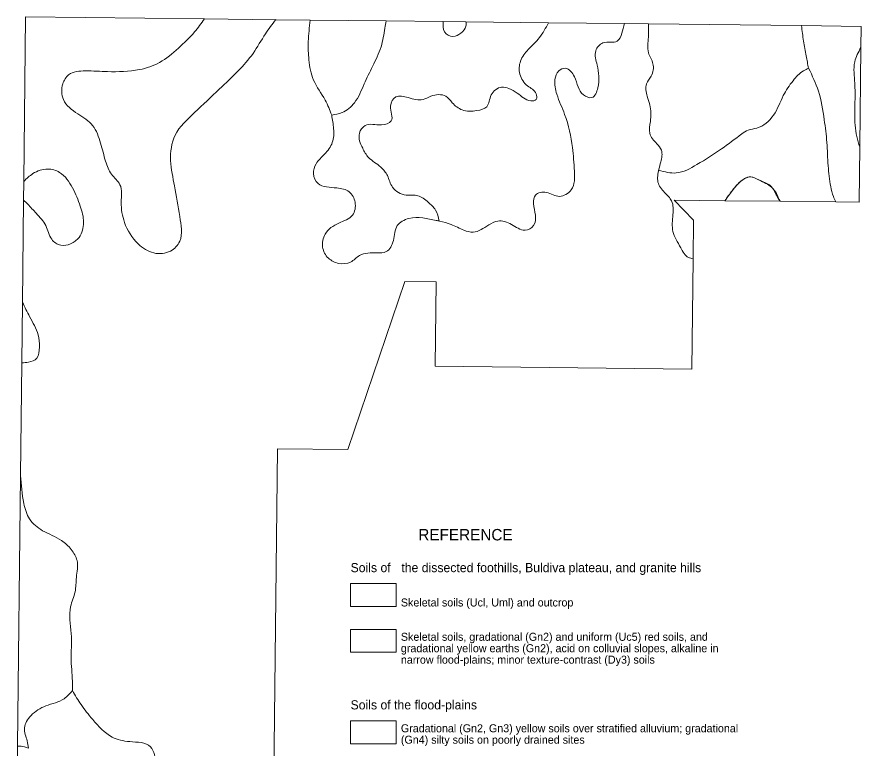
# Model space of a CAD drawing. Extents: x 796677 to 815296, y 8501154 to 8534584.
# Drawn here: x 796836 to 815296, y 8518597 to 8534584 of the extents above; entities that cross this region are included whole.
import ezdxf

# ---------------------------------------------------------------- set-up
doc = ezdxf.new("R2010")
doc.units = 0
doc.header["$LTSCALE"] = 70
for name, color, linetype, lineweight in [('30', 7, 'Continuous', 13), ('31', 7, 'Continuous', 13), ('32', 7, 'Continuous', 13), ('33', 7, 'Continuous', 13)]:
    doc.layers.add(name, color=color, linetype=linetype, lineweight=lineweight)
doc.layers.add('60', color=7, linetype='Continuous')

msp = doc.modelspace()

# ---------------------------------------------------------------- linework, layer by layer
at = {"layer": '30'}
for p, q in [((803251.08, 8534513.12), (802496.87, 8534521.65)), ((810645.75, 8534429.48), (810120.03, 8534435.43)), ((796983.21, 8530574.07), (796958.24, 8528327.65)), ((812316.38, 8530565.37), (813523.7, 8530551.45)), ((796943.71, 8527020.93), (796916.34, 8524559.34))]:
    msp.add_line(p, q, dxfattribs=at)
for points in [[(800936.16, 8534539.3), (797027.79, 8534583.51), (796987.84, 8530990.1)], [(802270.49, 8501474.58), (802331.51, 8506844.03), (800525.82, 8506864.46), (800607.09, 8514090.19), (802413.3, 8514069.87), (802537.73, 8525140.62), (804070.16, 8525123.41), (805316.55, 8528800.06), (806000.72, 8528792.3), (805979.73, 8526947.23), (811593.82, 8526882.94), (811621.58, 8529294.51)]]:
    msp.add_lwpolyline(points, dxfattribs=at)
msp.add_lwpolyline([(804132.47, 8521693.59), (805132.47, 8521693.59), (805132.47, 8522193.59), (804132.47, 8522193.59)], close=True, dxfattribs=at)
for points in [[(802498.04, 8534525.08), (802270.81, 8534212.39), (802000.97, 8533786), (801674.33, 8533402.25), (801262.48, 8533004.29), (800722.81, 8532492.62), (800296.76, 8531995.16), (800197.34, 8531440.85), (800282.55, 8530886.54), (800396.17, 8530218.53), (800396.17, 8529678.44), (800197.34, 8529465.24), (799828.1, 8529422.6), (799487.25, 8529621.59), (799189.01, 8530090.62), (799118.01, 8530531.22), (799089.6, 8530914.97), (798904.98, 8531142.38), (798777.16, 8531426.64), (798663.55, 8531824.6), (798493.13, 8532208.36), (798166.48, 8532464.19), (797854.04, 8532776.88), (797839.84, 8533117.99), (797967.66, 8533316.97), (798336.91, 8533402.25), (798819.77, 8533388.04), (799515.66, 8533430.68), (799955.91, 8533587.02), (800367.76, 8533899.71), (800722.81, 8534255.03), (800936.16, 8534539.3)], [(803719.39, 8532435.76), (803577.37, 8532762.66), (803321.74, 8533203.27), (803222.33, 8533643.87), (803208.13, 8534041.84), (803251.08, 8534513.12)], [(810120.03, 8534435.43), (810063.44, 8534226.61), (809964.02, 8534056.05), (809651.58, 8534013.41), (809495.36, 8533842.85), (809523.77, 8533530.17), (809537.97, 8533032.71), (809410.15, 8532819.52), (809225.53, 8532876.37), (809026.7, 8533274.33), (808827.88, 8533459.1), (808685.86, 8533402.25), (808600.65, 8533217.48), (808643.26, 8532890.58), (808813.68, 8532449.98), (808984.1, 8531725.11), (809026.7, 8531213.44), (808955.69, 8530801.27), (808700.06, 8530659.14), (808416.03, 8530744.41), (808174.6, 8530687.56), (808131.99, 8530502.79), (808174.6, 8530246.96), (808131.99, 8530019.55), (807947.37, 8529920.06), (807649.13, 8530047.98), (807350.89, 8530119.04), (807152.07, 8530033.76), (806811.22, 8529877.42), (806612.4, 8529920.06), (806328.36, 8530047.98), (806076.89, 8530119.04)], [(810872.94, 8531256.08), (810915.54, 8531412.43), (810929.75, 8531668.26), (810830.33, 8531810.39), (810674.11, 8532037.8), (810688.32, 8532293.63), (810674.11, 8532663.17), (810617.31, 8532847.94), (810603.1, 8533117.99), (810702.52, 8533288.55), (810745.12, 8533558.59), (810645.71, 8533800.21), (810645.71, 8534141.33), (810645.75, 8534429.48)], [(806076.89, 8530119.04), (806005.88, 8530133.25), (805409.41, 8530175.89), (805153.77, 8530019.55), (805068.56, 8529692.65), (804912.34, 8529451.03), (804713.52, 8529422.6), (804330.07, 8529365.75), (804131.24, 8529223.62), (803875.61, 8529195.19), (803648.38, 8529308.9), (803520.57, 8529550.52), (803577.37, 8529834.78), (803875.61, 8530076.4), (804173.85, 8530246.96), (804230.66, 8530531.22), (804102.84, 8530758.63), (803833, 8530843.91), (803421.15, 8530943.4), (803321.74, 8531156.59), (803378.55, 8531369.79), (803563.17, 8531582.98), (803733.59, 8531838.82), (803762, 8532137.29), (803719.39, 8532435.76)], [(796987.8, 8530986.35), (797186.56, 8531156.59), (797513.2, 8531256.08), (797768.83, 8531185.02), (798052.87, 8530843.91), (798223.29, 8530445.94), (798294.3, 8530090.62), (798194.89, 8529763.72), (798010.26, 8529621.59), (797797.24, 8529593.16), (797598.41, 8529721.08), (797470.6, 8530019.55), (797257.57, 8530289.6), (797072.95, 8530488.58), (796983.21, 8530574.07)], [(811621.58, 8529294.51), (811521.5, 8529323.11), (811351.08, 8529536.31), (811180.66, 8529891.63), (811180.66, 8530261.17), (811152.26, 8530559.65), (810996.04, 8530744.41), (810854.02, 8530971.82), (810872.94, 8531256.08)], [(813523.7, 8530551.45), (813503.76, 8530584.62), (813458.14, 8530660.5), (813314.39, 8530890.46), (813205.55, 8530958.26), (813008.28, 8531044.99), (812881.22, 8531085.83), (812746.26, 8531048.44), (812604.56, 8530933.06), (812476.78, 8530782.95), (812316.38, 8530565.37)], [(796958.4, 8528342.58), (797115.55, 8528029.73), (797300.17, 8527631.76), (797328.58, 8527361.71), (797271.77, 8527120.09), (797087.15, 8527034.82), (796943.71, 8527020.93)], [(796916.34, 8524559.34), (796987.38, 8523948.02), (797115.2, 8523606.91), (797399.23, 8523351.07), (797811.09, 8523137.88), (798024.11, 8522938.89), (798151.93, 8522697.27), (798137.73, 8522327.73), (798109.32, 8522015.05), (798009.91, 8521688.15), (798024.11, 8521105.41), (798024.11, 8520508.47), (798052.52, 8519996.8), (798052.52, 8519854.67)], [(798052.52, 8519854.67), (798238.43, 8519549.61), (798494.06, 8519222.71), (798920.11, 8518838.96), (799303.56, 8518739.47), (799758.02, 8518625.77), (799843.23, 8518455.21), (799885.83, 8518142.52), (800042.05, 8517701.92), (800070.46, 8517318.17), (800013.65, 8516948.63), (799814.83, 8516536.45), (799417.18, 8516095.85), (798721.29, 8515655.24)]]:
    msp.add_spline(points, degree=3, dxfattribs=at)
at = {"layer": '31'}
for p, q in [((804912.48, 8534494.33), (803251.08, 8534513.12)), ((806158.24, 8534480.24), (806655.07, 8534474.62)), ((808458.79, 8534454.22), (810120.03, 8534435.43)), ((810645.75, 8534429.48), (813993.04, 8534391.62)), ((815290.42, 8533913.69), (815265.16, 8531739.23)), ((796958.4, 8528342.58), (796943.71, 8527020.93))]:
    msp.add_line(p, q, dxfattribs=at)
msp.add_lwpolyline([(800936.16, 8534539.3), (802498, 8534521.64), (802498.04, 8534525.08)], dxfattribs=at)
msp.add_lwpolyline([(804132.47, 8520693.59), (805132.47, 8520693.59), (805132.47, 8521193.59), (804132.47, 8521193.59)], close=True, dxfattribs=at)
for points in [[(802498.04, 8534525.08), (802270.81, 8534212.39), (802000.97, 8533786), (801674.33, 8533402.25), (801262.48, 8533004.29), (800722.81, 8532492.62), (800296.76, 8531995.16), (800197.34, 8531440.85), (800282.55, 8530886.54), (800396.17, 8530218.53), (800396.17, 8529678.44), (800197.34, 8529465.24), (799828.1, 8529422.6), (799487.25, 8529621.59), (799189.01, 8530090.62), (799118.01, 8530531.22), (799089.6, 8530914.97), (798904.98, 8531142.38), (798777.16, 8531426.64), (798663.55, 8531824.6), (798493.13, 8532208.36), (798166.48, 8532464.19), (797854.04, 8532776.88), (797839.84, 8533117.99), (797967.66, 8533316.97), (798336.91, 8533402.25), (798819.77, 8533388.04), (799515.66, 8533430.68), (799955.91, 8533587.02), (800367.76, 8533899.71), (800722.81, 8534255.03), (800936.16, 8534539.3)], [(803251.08, 8534513.12), (803208.13, 8534041.84), (803222.33, 8533643.87), (803321.74, 8533203.27), (803577.37, 8532762.66), (803719.39, 8532435.76)], [(803719.39, 8532435.76), (803946.62, 8532492.62), (804216.45, 8532705.81), (804429.48, 8533117.99), (804614.1, 8533501.74), (804798.73, 8533928.13), (804883.94, 8534340.31), (804912.48, 8534494.33)], [(806655.07, 8534474.62), (806655, 8534382.95), (806541.39, 8534226.61), (806370.97, 8534155.54), (806186.34, 8534255.03), (806158.24, 8534480.24)], [(806070.15, 8530120.39), (805987.52, 8530360.66), (805831.3, 8530531.22), (805604.07, 8530673.35), (805348.44, 8530687.56), (805050.2, 8530858.12), (804936.58, 8531113.95), (804794.57, 8531298.72), (804524.73, 8531511.92), (804396.92, 8531710.9), (804325.91, 8532037.8), (804453.72, 8532208.36), (804808.77, 8532222.57), (805021.79, 8532307.85), (805007.59, 8532634.75), (805121.21, 8532833.73), (805391.04, 8532819.52), (805717.68, 8532776.88), (805888.1, 8532847.94), (806214.75, 8532847.94), (806356.76, 8532705.81), (806569.79, 8532549.47), (806896.43, 8532535.26), (807109.46, 8532620.53), (807208.87, 8532876.37), (807436.1, 8533046.92), (807592.32, 8533018.5), (807776.94, 8532919.01), (808075.18, 8532748.45), (808188.8, 8532776.88), (808188.8, 8532904.79), (808004.17, 8533075.35), (807833.75, 8533331.18), (807847.95, 8533615.45), (808018.38, 8533871.28), (808259.81, 8534127.11), (808458.79, 8534454.22)], [(810120.03, 8534435.43), (810063.44, 8534226.61), (809964.02, 8534056.05), (809651.58, 8534013.41), (809495.36, 8533842.85), (809523.77, 8533530.17), (809537.97, 8533032.71), (809410.15, 8532819.52), (809225.53, 8532876.37), (809026.7, 8533274.33), (808827.88, 8533459.1), (808685.86, 8533402.25), (808600.65, 8533217.48), (808643.26, 8532890.58), (808813.68, 8532449.98), (808984.1, 8531725.11), (809026.7, 8531213.44), (808955.69, 8530801.27), (808700.06, 8530659.14), (808416.03, 8530744.41), (808174.6, 8530687.56), (808131.99, 8530502.79), (808174.6, 8530246.96), (808131.99, 8530019.55), (807947.37, 8529920.06), (807649.13, 8530047.98), (807350.89, 8530119.04), (807152.07, 8530033.76), (806811.22, 8529877.42), (806612.4, 8529920.06), (806328.36, 8530047.98), (806076.89, 8530119.04)], [(810872.94, 8531256.08), (810915.54, 8531412.43), (810929.75, 8531668.26), (810830.33, 8531810.39), (810674.11, 8532037.8), (810688.32, 8532293.63), (810674.11, 8532663.17), (810617.31, 8532847.94), (810603.1, 8533117.99), (810702.52, 8533288.55), (810745.12, 8533558.59), (810645.71, 8533800.21), (810645.71, 8534141.33), (810645.75, 8534429.48)], [(813993.04, 8534391.62), (814035.22, 8534056.05), (814092.03, 8533729.15), (814148.84, 8533459.1)], [(815265.16, 8531739.23), (815199.77, 8531966.73), (815157.17, 8532464.19), (815157.17, 8533132.2), (815157.17, 8533601.23), (815290.42, 8533913.69)], [(814148.84, 8533459.1), (814035.22, 8533402.25), (813807.99, 8533189.05), (813594.97, 8532862.16), (813381.94, 8532435.76), (813012.69, 8532151.5), (812828.07, 8532108.86), (812686.05, 8532023.59), (812245.79, 8531696.69), (811706.13, 8531355.57), (811251.67, 8531170.81), (810871.22, 8531230.29)], [(796943.71, 8527020.93), (797087.15, 8527034.82), (797271.77, 8527120.09), (797328.58, 8527361.71), (797300.17, 8527631.76), (797115.55, 8528029.73), (796958.4, 8528342.58)], [(798052.52, 8519854.67), (797869.18, 8519677.53), (797471.53, 8519521.19), (797144.89, 8519307.99), (797002.87, 8519037.94), (797059.68, 8518753.68), (797088.08, 8518597.34)], [(798721.29, 8515655.24), (799417.18, 8516095.85), (799814.83, 8516536.45), (800013.65, 8516948.63), (800070.46, 8517318.17), (800042.05, 8517701.92), (799885.83, 8518142.52), (799843.23, 8518455.21), (799758.02, 8518625.77), (799303.56, 8518739.47), (798920.11, 8518838.96), (798494.06, 8519222.71), (798238.43, 8519549.61), (798052.52, 8519854.67)]]:
    msp.add_spline(points, degree=3, dxfattribs=at)
at = {"layer": '32'}
for p, q in [((804912.48, 8534494.33), (806158.24, 8534480.24)), ((806655.07, 8534474.62), (808458.79, 8534454.22)), ((813523.7, 8530551.45), (814745.38, 8530537.37))]:
    msp.add_line(p, q, dxfattribs=at)
for points in [[(796983.21, 8530574.07), (796987.87, 8530992.9), (796987.8, 8530986.35)], [(811621.58, 8529294.51), (811631.27, 8530136.2), (811208.21, 8530578.14), (812316.38, 8530565.37)], [(796850.5, 8518639.07), (796916.33, 8524559.34), (796916.34, 8524559.34)]]:
    msp.add_lwpolyline(points, dxfattribs=at)
msp.add_lwpolyline([(804132.47, 8518693.59), (805132.47, 8518693.59), (805132.47, 8519193.59), (804132.47, 8519193.59)], close=True, dxfattribs=at)
for points in [[(803719.39, 8532435.76), (803946.62, 8532492.62), (804216.45, 8532705.81), (804429.48, 8533117.99), (804614.1, 8533501.74), (804798.73, 8533928.13), (804883.94, 8534340.31), (804912.48, 8534494.33)], [(806158.24, 8534480.24), (806186.34, 8534255.03), (806370.97, 8534155.54), (806541.39, 8534226.61), (806655, 8534382.95), (806655.07, 8534474.62)], [(808458.79, 8534454.22), (808259.81, 8534127.11), (808018.38, 8533871.28), (807847.95, 8533615.45), (807833.75, 8533331.18), (808004.17, 8533075.35), (808188.8, 8532904.79), (808188.8, 8532776.88), (808075.18, 8532748.45), (807776.94, 8532919.01), (807592.32, 8533018.5), (807436.1, 8533046.92), (807208.87, 8532876.37), (807109.46, 8532620.53), (806896.43, 8532535.26), (806569.79, 8532549.47), (806356.76, 8532705.81), (806214.75, 8532847.94), (805888.1, 8532847.94), (805717.68, 8532776.88), (805391.04, 8532819.52), (805121.21, 8532833.73), (805007.59, 8532634.75), (805021.79, 8532307.85), (804808.77, 8532222.57), (804453.72, 8532208.36), (804325.91, 8532037.8), (804396.92, 8531710.9), (804524.73, 8531511.92), (804794.57, 8531298.72), (804936.58, 8531113.95), (805050.2, 8530858.12), (805348.44, 8530687.56), (805604.07, 8530673.35), (805831.3, 8530531.22), (805987.52, 8530360.66), (806070.15, 8530120.39)], [(814148.84, 8533459.1), (814035.22, 8533402.25), (813807.99, 8533189.05), (813594.97, 8532862.16), (813381.94, 8532435.76), (813012.69, 8532151.5), (812828.07, 8532108.86), (812686.05, 8532023.59), (812245.79, 8531696.69), (811706.13, 8531355.57), (811251.67, 8531170.81), (810871.22, 8531230.29)], [(814745.38, 8530537.37), (814688.51, 8530659.14), (814631.7, 8530872.33), (814574.89, 8531327.15), (814546.49, 8531838.82), (814489.68, 8532336.27), (814361.86, 8532961.65), (814148.84, 8533459.1)], [(806076.89, 8530119.04), (806005.88, 8530133.25), (805409.41, 8530175.89), (805153.77, 8530019.55), (805068.56, 8529692.65), (804912.34, 8529451.03), (804713.52, 8529422.6), (804330.07, 8529365.75), (804131.24, 8529223.62), (803875.61, 8529195.19), (803648.38, 8529308.9), (803520.57, 8529550.52), (803577.37, 8529834.78), (803875.61, 8530076.4), (804173.85, 8530246.96), (804230.66, 8530531.22), (804102.84, 8530758.63), (803833, 8530843.91), (803421.15, 8530943.4), (803321.74, 8531156.59), (803378.55, 8531369.79), (803563.17, 8531582.98), (803733.59, 8531838.82), (803762, 8532137.29), (803719.39, 8532435.76)], [(796987.8, 8530986.35), (797186.56, 8531156.59), (797513.2, 8531256.08), (797768.83, 8531185.02), (798052.87, 8530843.91), (798223.29, 8530445.94), (798294.3, 8530090.62), (798194.89, 8529763.72), (798010.26, 8529621.59), (797797.24, 8529593.16), (797598.41, 8529721.08), (797470.6, 8530019.55), (797257.57, 8530289.6), (797072.95, 8530488.58), (796983.21, 8530574.07)], [(810872.94, 8531256.08), (810854.02, 8530971.82), (810996.04, 8530744.41), (811152.26, 8530559.65), (811180.66, 8530261.17), (811180.66, 8529891.63), (811351.08, 8529536.31), (811521.5, 8529323.11), (811621.58, 8529294.51)], [(812316.38, 8530565.37), (812416.22, 8530701.78), (812600.84, 8530929.18), (812884.88, 8531085.53), (813069.5, 8531014.46), (813339.33, 8530858.12), (813523.7, 8530551.45)], [(796916.34, 8524559.34), (796987.38, 8523948.02), (797115.2, 8523606.91), (797399.23, 8523351.07), (797811.09, 8523137.88), (798024.11, 8522938.89), (798151.93, 8522697.27), (798137.73, 8522327.73), (798109.32, 8522015.05), (798009.91, 8521688.15), (798024.11, 8521105.41), (798024.11, 8520508.47), (798052.52, 8519996.8), (798052.52, 8519854.67)], [(798052.52, 8519854.67), (797869.18, 8519677.53), (797471.53, 8519521.19), (797144.89, 8519307.99), (797002.87, 8519037.94), (797059.68, 8518753.68), (797088.08, 8518597.34)], [(797088.08, 8518597.34), (797002.87, 8518625.77), (796850.53, 8518640.09)]]:
    msp.add_spline(points, degree=3, dxfattribs=at)
at = {"layer": '33'}
msp.add_line((796836.14, 8517346.39), (796850.52, 8518640.09), dxfattribs=at)
for points in [[(813993.04, 8534391.62), (815295.8, 8534376.89), (815290.42, 8533913.69)], [(815265.16, 8531739.23), (815251.13, 8530531.54), (814745.38, 8530537.37)]]:
    msp.add_lwpolyline(points, dxfattribs=at)
for points in [[(814148.84, 8533459.1), (814092.03, 8533729.15), (814035.22, 8534056.05), (813993.04, 8534391.62)], [(815290.42, 8533913.69), (815157.17, 8533601.23), (815157.17, 8533132.2), (815157.17, 8532464.19), (815199.77, 8531966.73), (815265.16, 8531739.23)], [(814745.38, 8530537.37), (814688.51, 8530659.14), (814631.7, 8530872.33), (814574.89, 8531327.15), (814546.49, 8531838.82), (814489.68, 8532336.27), (814361.86, 8532961.65), (814148.84, 8533459.1)], [(796850.53, 8518640.09), (797002.87, 8518625.77), (797088.08, 8518597.34)]]:
    msp.add_spline(points, degree=3, dxfattribs=at)

# ---------------------------------------------------------------- texts
at = {"layer": '60'}
for s, height, p in [('REFERENCE', 250, (805613.88, 8523138.16)), ('Soils of', 200, (804132.47, 8522443.59)), ('the dissected foothills, Buldiva plateau, and granite hills', 200, (805242.47, 8522443.59)), ('Skeletal soils (Ucl, Uml) and outcrop', 175, (805232.47, 8521693.59)), ('Skeletal soils, gradational (Gn2) and uniform (Uc5) red soils, and', 175, (805232.47, 8520943.59)), ('gradational yellow earths (Gn2), acid on colluvial slopes, alkaline in', 175, (805232.47, 8520693.59)), ('narrow flood-plains; minor texture-contrast (Dy3) soils', 175, (805232.47, 8520443.59)), ('Soils of the flood-plains', 200, (804132.47, 8519443.59)), ('Gradational (Gn2, Gn3) yellow soils over stratified alluvium; gradational', 175, (805232.47, 8518943.59)), ('(Gn4) silty soils on poorly drained sites', 175, (805232.47, 8518693.59))]:
    msp.add_text(s, height=height, dxfattribs=at).set_placement(p)

doc.saveas('drawing.dxf')
